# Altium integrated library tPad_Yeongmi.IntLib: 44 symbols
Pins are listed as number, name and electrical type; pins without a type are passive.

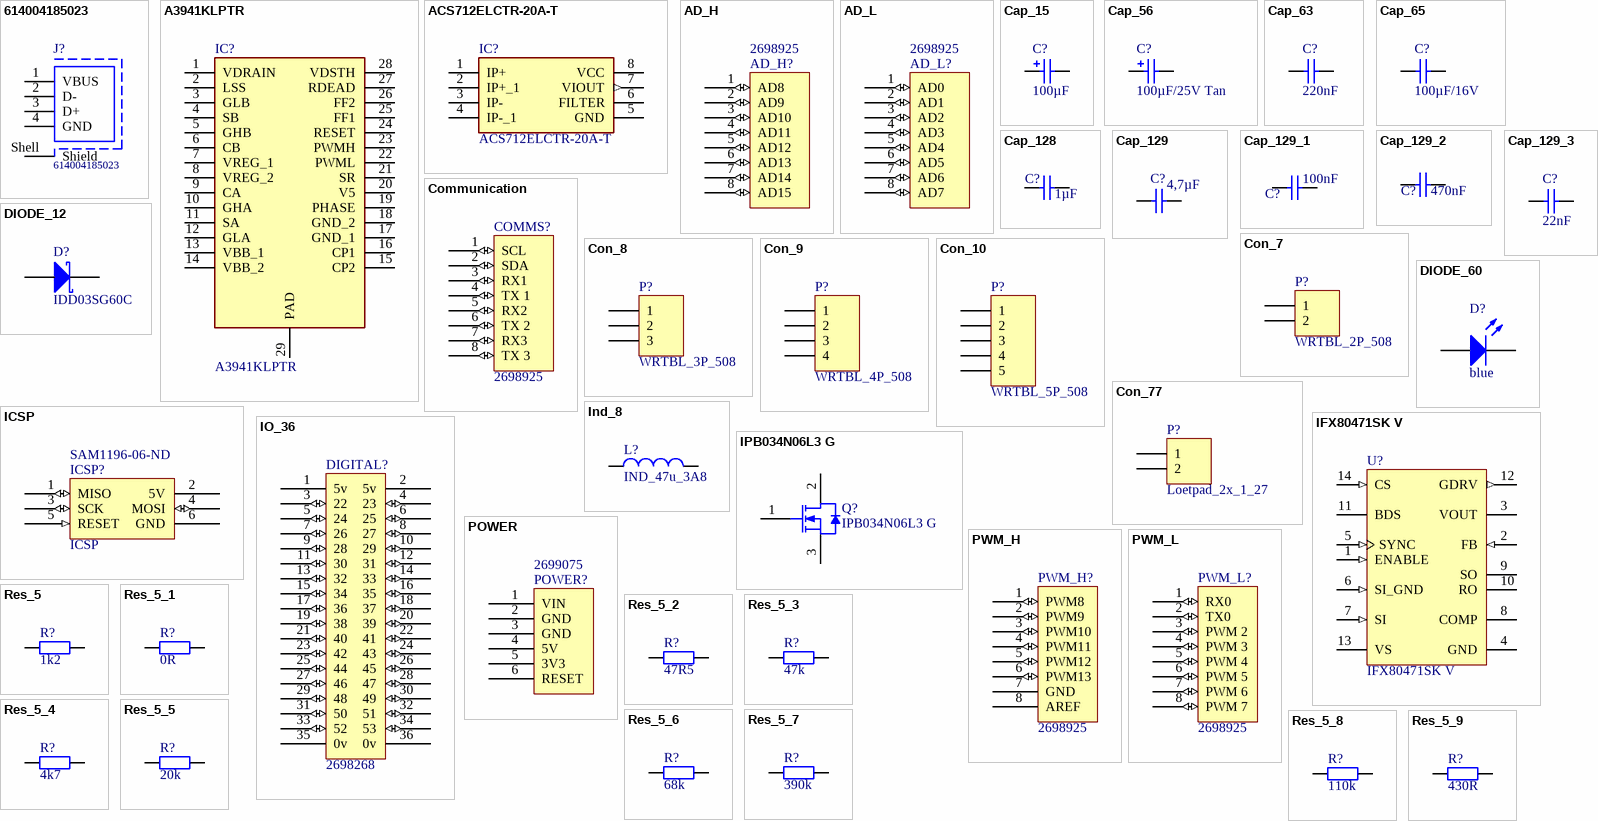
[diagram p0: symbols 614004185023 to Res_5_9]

## 614004185023
designator J?
USB 2.0 Type A Receptacle WR-COM, Vertical, THT, Short Type; Rated Current: 1.5 A; Contact Resistance: 30 mOhm; Working Voltage: 30 VAC
footprint 614004185023
footprint 614004185023 (USB 2.0 Type A Vertical Short Type THT)
pins: 1 VBUS, 2 D-, 3 D+, 4 GND, Shell Shield

## A3941KLPTR
designator IC?
Integrated Circuit; Manufacturer_Name: Allegro Microsystems
footprint SOP65P640X120-29N
footprint SOP65P640X120-29N
footprint SOP65P640X120-29N
pins: 1 VDRAIN, 2 LSS, 3 GLB, 4 SB, 5 GHB, 6 CB, 7 VREG_1, 8 VREG_2, 9 CA, 10 GHA, 11 SA, 12 GLA, 13 VBB_1, 14 VBB_2, 15 CP2, 16 CP1, 17 GND_1, 18 GND_2, 19 PHASE, 20 V5, 21 SR, 22 PWML, 23 PWMH, 24 RESET, 25 FF1, 26 FF2, 27 RDEAD, 28 VDSTH, 29 PAD

## ACS712ELCTR-20A-T
designator IC?
Integrated Circuit; Manufacturer_Name: Allegro Microsystems; Allied_Number: R1076682
footprint SOIC127P600X175-8N
footprint SOIC127P600X175-8N
footprint SOIC127P600X175-8N
pins: 1 IP+, 2 IP+_1, 3 IP-, 4 IP-_1, 5 GND (power), 6 FILTER, 7 VIOUT (out), 8 VCC (power)

## AD_H
designator AD_H?  Supplier Part Number 4: 2698925  (hidden comment: AD_H)
footprint Header 8x1 8.5mm (Stackable 8 pin header)
pins: 1 AD8 (io), 2 AD9 (io), 3 AD10 (io), 4 AD11 (io), 5 AD12 (io), 6 AD13 (io), 7 AD14 (io), 8 AD15 (io)

## AD_L
designator AD_L?  Supplier Part Number 5: 2698925  (hidden comment: AD_L)
footprint Header 8x1 8.5mm (Stackable 8 pin header)
pins: 1 AD0 (io), 2 AD1 (io), 3 AD2 (io), 4 AD3 (io), 5 AD4 (io), 6 AD5 (io), 7 AD6 (io), 8 AD7 (io)

## Cap_15
designator C?, comment 100µF
Name: Cap_Elko_rad_100u_35V; RS_number: 228-6767; QR: 1; ax_rad: rad; Capacity: 100u; Voltage: 35V
footprint Cap_THT_Elko_rad_D8mm
pins: 1, 2
1 alternate drawing of the same symbol

## Cap_56
designator C?, comment 100µF/25V Tan
Name: Cap_tan_47u_25V; RS_number: 684-5284P; QR: 1; Capacity: 47u; Voltage: 25v
footprint C
pins: 1, 2
1 alternate drawing of the same symbol

## Cap_63
designator C?, comment 220nF
Name: Cap_0805; Capacity: ?F; Voltage: ?V
footprint _0805
pins: 1, 2

## Cap_65
designator C?, comment 100µF/16V
Name: Cap_1210; Capacity: ?F; Voltage: ?V
footprint _1210
pins: 1, 2

## Cap_128
designator C?, comment 1µF
Name: Cap_0805; QR: 0
footprint _0805
pins: 1, 2

## Cap_129
designator C?, comment 4,7µF
Name: Cap_0603; QR: 0
footprint _0603
pins: 1, 2

## Cap_129_1
designator C?, comment 100nF
Name: Cap_0603; QR: 0
footprint _0603
pins: 1, 2

## Cap_129_2
designator C?, comment 470nF
Name: Cap_0603; QR: 0
footprint _0603
pins: 1, 2

## Cap_129_3
designator C?, comment 22nF
Name: Cap_0603; QR: 0
footprint _0603
pins: 1, 2

## Communication
designator COMMS?  Supplier Part Number 4: 2698925  (hidden comment: Communication)
footprint Header 8x1 8.5mm (Stackable 8 pin header)
pins: 1 SCL (io), 2 SDA (io), 3 RX1 (io), 4 TX 1 (io), 5 RX2 (io), 6 TX 2 (io), 7 RX3 (io), 8 TX 3 (io)

## Con_7
designator P?, comment WRTBL_2P_508
RS_number: 193-0586; QR: 0
footprint WRTBL_2P_508
pins: 1, 2

## Con_8
designator P?, comment WRTBL_3P_508
QR: 0
footprint WRTBL_3P_508
pins: 1, 2, 3

## Con_9
designator P?, comment WRTBL_4P_508
QR: 0
footprint WRTBL_4P_508
pins: 1, 2, 3, 4

## Con_10
designator P?, comment WRTBL_5P_508
QR: 0
footprint WRTBL_5P_508
pins: 1, 2, 3, 4, 5

## Con_77
designator P?, comment Loetpad_2x_1_27
footprint Loetpad_2x_1_27
pins: 1, 2

## DIODE_12
designator D?, comment IDD03SG60C
Name: 30WQ06FN; Type: Schottky; Current / Power: 3.5 A; RS_number: 300-357P; QR: 0
footprint TO_252
pins: 1, 2, 3

## DIODE_60
designator D?, comment blue
Name: LED_0603_blau; Type: LED; Colour: blau; RS_number: 697-3610P; QR: 0
footprint LED_0603
pins: 1, 2

## ICSP
designator ICSP?  Supplier Part Number 5: SAM1196-06-ND
footprint ICSP
pins: 1 MISO (io), 2 5V (power), 3 SCK (io), 4 MOSI (io), 5 RESET (in), 6 GND (power)

## IFX80471SK V
designator U?
Step-Down DC/DC Controller, 2,300 mA Iq, -40 to 125 degC, PG-DSO-14-1, Reel, Green; Manufacturer: Infineon; Green: TRUE; Iq (typ): 130 uA; Max Number Reflow: 3; Max Peak Reflow Temp: 260 degC; Output: Buck Converter; Tolerance: 3(5)%; VQ (max): adjustable
footprint INF-PG-DSO-14-1_N (SOP, 14-Leads, Body 8.65x3.9mm, Pitch 1.27mm, IPC Medium Density)
footprint INF-PG-DSO-14-1_L (SOP, 14-Leads, Body 8.65x3.9mm, Pitch 1.27mm, IPC High Density)
footprint INF-PG-DSO-14-1_M (SOP, 14-Leads, Body 8.65x3.9mm, Pitch 1.27mm, IPC Low Density)
pins: 1 ENABLE (in) "Active-High enable input (only adjustable version, IFX80471SKV) for the  device.  The device is shut down when ENABLE is driven low. In this shut down-mode the  reference, the output and the external MOSFET are turned off. (See Datasheet)", 2 FB (in) "Feedback input. 1. For adjustable version (IFX80471SKV) connect this pin to an external voltage  divider from the output to GND (see Chapter 7.2). 2. For the 5V fixed output voltage version (IFX80471SKV50) the FB is (See Datasheet)", 3 VOUT (power) "Buck output voltage input. Input for the internal supply. Connect always to the output of the buck converter  (output capacitor).", 4 GND (power) "Ground connection. Analog signal ground", 5 SYNC (in) "Input for external frequency synchronization.  An external clock signal connected to this pin allows switching frequency  synchronization of the device. The internal oscillator is clocked then by the  frequency applied at (See Datasheet)", 6 SI_GND (in) "SI-Ground input.  Ground connection for SI comparator resistor divider. Depending on SI_ENABLE  this input is switched to high impedance or low ohmic to GND.", 7 SI (in) "Sense comparator input.  Input of the low-battery comparator. This input is compared to an internal 1.25V  reference where SO gives the result of the comparison. Can be used for any  comparison, not necessarily as battery (See Datasheet)", 8 COMP "Compensation input. Connect via RC-compensation network to GND.", 9 SO (oc) "Sense comparator output.  Open drain output from SI comparator at the adjustable version (IFX80471SKV), Pull down structure with an internal 20kohm pull up resistor to VOUT at the 5V version  (IFX80471SKV50).", 10 RO (oc) "Reset output.  Open drain output from undervoltage reset comparator at the adjustable version  (IFX80471SKV), Pull down structure with an internal 20kohm pull up resistor to VOUT at the 5V version  (IFX80471SKV50).", 11 BDS (power) "Buck driver supply input.  Connect a ceramic capacitor between BDS and VS to generate clamped gatesource voltage to supply the driver of the PMOS power stage.", 12 GDRV (out) "Gate drive output. Connect to the gate of the external P-Channel MOSFET. The voltage at GDRV  swings between the levels of VS and BDS.", 13 VS (power) "Device supply input.  Connect a 220nF ceramic cap close to the pin in addition to the low ESR tantalum  input capacitance.", 14 CS (in) "Current-sense input.  Connect current-sense resistor between VS and CS. The voltage drop over the  sense-resistor determines the peak current flowing in the buck circuit. The external  MOSFET is turned off when the peak (See Datasheet)"

## Ind_8
designator L?, comment IND_47u_3A8
Inductor; Wuerth_number: 744 7709 470; QR: 0; Inductivity: 47 uH; Current: 3.8 A
footprint WE_PD_XXL
pins: 1, 2

## IO_36
designator DIGITAL?  Supplier Part Number 5: 2698268  (hidden comment: IO_36)
footprint HEADER 36X 8MM (Stackable 10 pin header)
pins: 1 5v (power), 2 5v (power), 3 22 (io) "Digital 22", 4 23 (io) "Digital 23", 5 24 (io) "Digital 24", 6 25 (io) "Digital 25", 7 26 (io) "Digital 26", 8 27 (io) "Digital 27", 9 28 (io) "Digital 28", 10 29 (io) "Digital 29", 11 30 (io) "Digital 30", 12 31 (io) "Digital 31", 13 32 (io) "Digital 32", 14 33 (io) "Digital 33", 15 34 (io) "Digital 34", 16 35 (io) "Digital 35", 17 36 (io) "Digital 36", 18 37 (io) "Digital 37", 19 38 (io) "Digital 38", 20 39 (io) "Digital 39", 21 40 (io) "Digital 40", 22 41 (io) "Digital 41", 23 42 (io) "Digital 42", 24 43 (io) "Digital 43", 25 44 (io) "Digital 44", 26 45 (io) "Digital 45", 27 46 (io) "Digital 46", 28 47 (io) "Digital 47", 29 48 (io) "Digital 48", 30 49 (io) "Digital 49", 31 50 (io) "Digital 50", 32 51 (io) "Digital 51", 33 52 (io) "Digital 52", 34 53 (io) "Digital 53", 35 0v (power), 36 0v (power)

## IPB034N06L3 G
designator Q?
N-Channel OptiMOS 3 Power-Transistor, 60 V VDS, 90 A ID, -55 to 175 degC, PG-TO-263-3-2, Reel, Green; Manufacturer: Infineon; Green: TRUE; ID (max): 90 A; IDpuls (max): 360 A; Polarity: N; Ptot (max): 167 W; QG: 59 nC; RDS (on) (max): 3.7 mOhm; RDS (on) (max) (@4.5V): 5.7 mOhm; Rth: 0.9 K/W; RthJA (max): 62 K/W; VDS (max): 60 V; VGS(th) (max): 2.2 V; VGS(th) (min): 1.2 V
footprint INF-PG-TO-263-3-2_A_N (DPAK, 3-Leads, Body 10.06x8.98mm, Pitch 2.54mm, IPC Medium Density)
footprint INF-PG-TO-263-3-2_A_L (DPAK, 3-Leads, Body 10.06x8.98mm, Pitch 2.54mm, IPC High Density)
footprint INF-PG-TO-263-3-2_A_M (DPAK, 3-Leads, Body 10.06x8.98mm, Pitch 2.54mm, IPC Low Density)
footprint INF-PG-TO-263-3-2_A_N
footprint INF-PG-TO-263-3-2_A_N
footprint INF-PG-TO-263-3-2_A_N
pins: 1 GATE, 2 DRAIN, 3 SOURCE

## POWER
designator POWER?  Supplier Part Number 2: 2699075  (hidden comment: POWER)
footprint Header 6x1 8.5mm (Stackable 6 pin header)
pins: 1 VIN (power), 2 GND (power), 3 GND (power), 4 5V (power), 5 3V3 (power), 6 RESET

## PWM_H
designator PWM_H?  Supplier Part Number 4: 2698925  (hidden comment: PWM_H)
footprint Header 8x1 8.5mm (Stackable 8 pin header)
pins: 1 PWM8 (io) "PWM 8", 2 PWM9 (io) "PWM 9", 3 PWM10 (io) "PWM 10", 4 PWM11 (io) "PWM 11", 5 PWM12 (io) "PWM 12", 6 PWM13 (io) "PWM 13", 7 GND (power), 8 AREF

## PWM_L
designator PWM_L?  Supplier Part Number 4: 2698925  (hidden comment: PWM_L)
footprint Header 8x1 8.5mm (Stackable 8 pin header)
pins: 1 RX0 (io) "PWM 0 & RX0", 2 TX0 (io) "PWM 1 & TX0", 3 PWM 2 (io), 4 PWM 3 (io), 5 PWM 4 (io), 6 PWM 5 (io), 7 PWM 6 (io), 8 PWM 7 (io)

## Res_5
designator R?, comment 1k2
Name: Res_0603
footprint _0603
pins: 1, 2

## Res_5_1
designator R?, comment 0R
Name: Res_0603
footprint _0603
pins: 1, 2

## Res_5_2
designator R?, comment 47R5
Name: Res_0603
footprint _0603
pins: 1, 2

## Res_5_3
designator R?, comment 47k
Name: Res_0603
footprint _0603
pins: 1, 2

## Res_5_4
designator R?, comment 4k7
Name: Res_0603
footprint _0603
pins: 1, 2

## Res_5_5
designator R?, comment 20k
Name: Res_0603
footprint _0603
pins: 1, 2

## Res_5_6
designator R?, comment 68k
Name: Res_0603
footprint _0603
pins: 1, 2

## Res_5_7
designator R?, comment 390k
Name: Res_0603
footprint _0603
pins: 1, 2

## Res_5_8
designator R?, comment 110k
Name: Res_0603
footprint _0603
pins: 1, 2

## Res_5_9
designator R?, comment 430R
Name: Res_0603
footprint _0603
pins: 1, 2

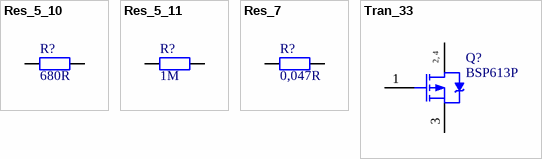
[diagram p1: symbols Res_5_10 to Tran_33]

## Res_5_10
designator R?, comment 680R
Name: Res_0603
footprint _0603
pins: 1, 2

## Res_5_11
designator R?, comment 1M
Name: Res_0603
footprint _0603
pins: 1, 2

## Res_7
designator R?, comment 0,047R
Name: Res_1206
footprint _1206
pins: 1, 2

## Tran_33
designator Q?, comment BSP613P
P-Channel SIPMOS Small-Signal-Transistor, -60 V VDS, -2.9 A ID, -55 to 150 degC, PG-SOT223 (SC-73), Reel, Green; Manufacturer: Infineon; Green: TRUE; ID (max): -2.9 A; IDpuls (max): -11.6 A; Mode: Enhancement; Polarity: P; Pto t (max): 1.8 W; QG: -22 nC; RDS (on) (max): 130 mOhm; Rth: 100 K/W; VDS (max): -60 V; VGS(th) (max): -4 V; VGS(th) (min): -2.1 V
footprint INF-PG-SOT223_SC-73_N (SOT223, 4-Leads, Body 6.5x3.5mm, Pitch 2.3mm, IPC Medium Density)
footprint INF-PG-SOT223_SC-73_L (SOT223, 4-Leads, Body 6.5x3.5mm, Pitch 2.3mm, IPC High Density)
footprint INF-PG-SOT223_SC-73_M (SOT223, 4-Leads, Body 6.5x3.5mm, Pitch 2.3mm, IPC Low Density)
pins: 1 GATE, 2 DRAIN, 3 SOURCE, 4 DRAIN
